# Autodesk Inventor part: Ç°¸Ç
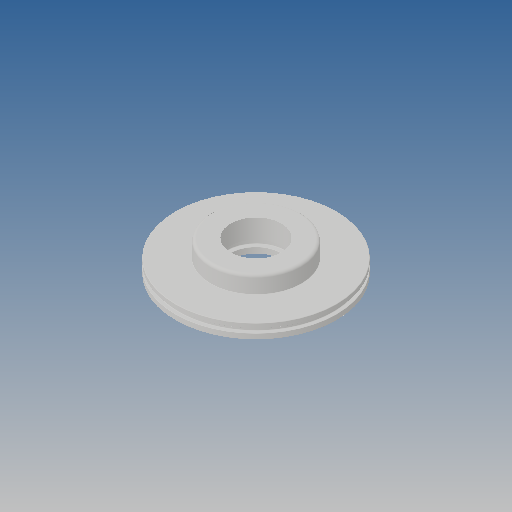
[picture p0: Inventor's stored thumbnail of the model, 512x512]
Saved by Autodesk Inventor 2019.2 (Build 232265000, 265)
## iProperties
Created: 2013-07
Part Number: Ç°¸Ç
Material: Ogólny
Document SubType Name: Modeling
Designer: CADENGINEERING4
Density: 1 g/cm^3
Appearance: Domyślna
Author: CADENGINEERING4
Revision Number: ÈÎºÎ
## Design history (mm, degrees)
feature "Ðý×ª1"
node "Bryła1"
